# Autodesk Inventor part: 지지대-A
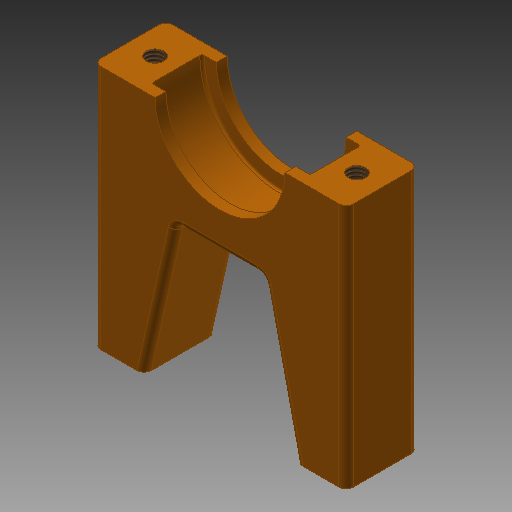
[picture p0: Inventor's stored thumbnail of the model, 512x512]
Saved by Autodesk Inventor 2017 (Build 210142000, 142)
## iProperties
Created: 2018-01
Part Number: 지지대-A
Material: 알루미늄 6061
Document SubType Name: Modeling
Designer: mduedu
Density: 2.71 g/cm^3
Mass: 18.1629 g
Surface Area: 35.102 cm^2
Volume: 6.70218 cm^3
Appearance: 주황색
Author: mduedu
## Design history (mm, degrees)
sketch "스케치1"
  geometry: L1 (-17.5, 0)-(17.5, 0); L2 (17.5, 0)-(17.5, 34); L3 (17.5, 34)-(-17.5, 34); L4 (-17.5, 34)-(-17.5, 0); 3 further points
  constraints: 8 end point, 2 midpoint, 1 coincident, 1 horizontal, 1 parallel, 1 vertical, 1 vertical alignment
  dimensions: "d3" = 35 distance of L2.end L3.end; "d4" = 34 distance of L1.end L2.end
extrude "돌출1" new body sketch "스케치1" stored distance "d5" = 10; taper "d6" = 0 deg
sketch "스케치2"
  geometry: L1 (-10.5, 0)-(10.5, 0); L2 (10.5, 0)-(6, 20); L3 (6, 20)-(-6, 20); L4 (-6, 20)-(-10.5, 0); L5 (-17.5, 0)-(17.5, 0) reference; 4 further points
  constraints: 8 end point, 4 midpoint, 1 horizontal, 1 parallel, 1 vertical alignment
  dimensions: "d10" = 20 distance between parallel lines of L1 L3; "d38" = 12 distance of L3.end L2.end; "d39" = 7 distance of L1.start L5.start
extrude "돌출2" cut sketch "스케치2" stored distance "d11" = 10; taper "d12" = 0 deg
sketch "스케치3"
  geometry: L1 (-17.5, 34)-(17.5, 34) reference; C1 r 11 at (0, 34); C2 r 9 at (0, 34); 1 further point
  constraints: 2 centre point, 1 coincident, 1 midpoint
  dimensions: "d13" = 22 diameter of C1; "d16" = 18 diameter of C2
extrude "돌출3" cut sketch "스케치3" stored distance "d14" = 7; taper "d15" = 0 deg
extrude "돌출4" cut sketch "스케치3" stored distance "d17" = 7; taper "d18" = 0 deg
fillet "모깎기1" dims "d19" = 0.3
fillet "모깎기2" dims "d20" = 1
fillet "모깎기3" dims "d21" = 1
fillet "모깎기4" dims "d22" = 1
sketch "스케치4"
  geometry: L1 (-26.5, -7.5)-(-26.5, 0.5) reference; L2 (8.5, 0.5)-(8.5, -7.5) reference; L3 (-20.525, 1.5)-(-25.5, 1.5) reference; 2 further points
  constraints: 1 horizontal alignment
  dimensions: "d43" = 3.5 distance from line of point (-23, -3.5) L1; "d45" = 28 distance of point (5, -3.5) point (-23, -3.5); "d46" = 5 distance from line of L3 point (-23, -3.5)
hole "구멍1" sketch "스케치4" at (-23, -3.5), (5, -3.5) diameter "d23" = 2.459; stored, may be unused: countersink angle "d27" = 90 deg, drill point angle "d29" = 120 deg; dims "d24" = 4.5, "d25" = 4, "d26" = 2, "d28" = 6
sketch "스케치5"
  geometry: L1 (1, 9)-(5.975, 9) reference; L2 (0, 8)-(0, 0) reference; L3 (35, 0)-(35, 8) reference; 4 further points
  constraints: 1 horizontal alignment, 1 other
  dimensions: "d40" = 5 distance from line of L1 point (3.5, 4); "d41" = 3.5 distance from line of L2 point (3.5, 4); "d42" = 3.5 distance from line of L3 point (31.5, 4)
hole "구멍2" sketch "스케치5" diameter "d30" = 2.459; stored, may be unused: countersink angle "d34" = 90 deg, drill point angle "d36" = 120 deg; dims "d31" = 6, "d32" = 4, "d33" = 2, "d35" = 8
node "솔리드1"
